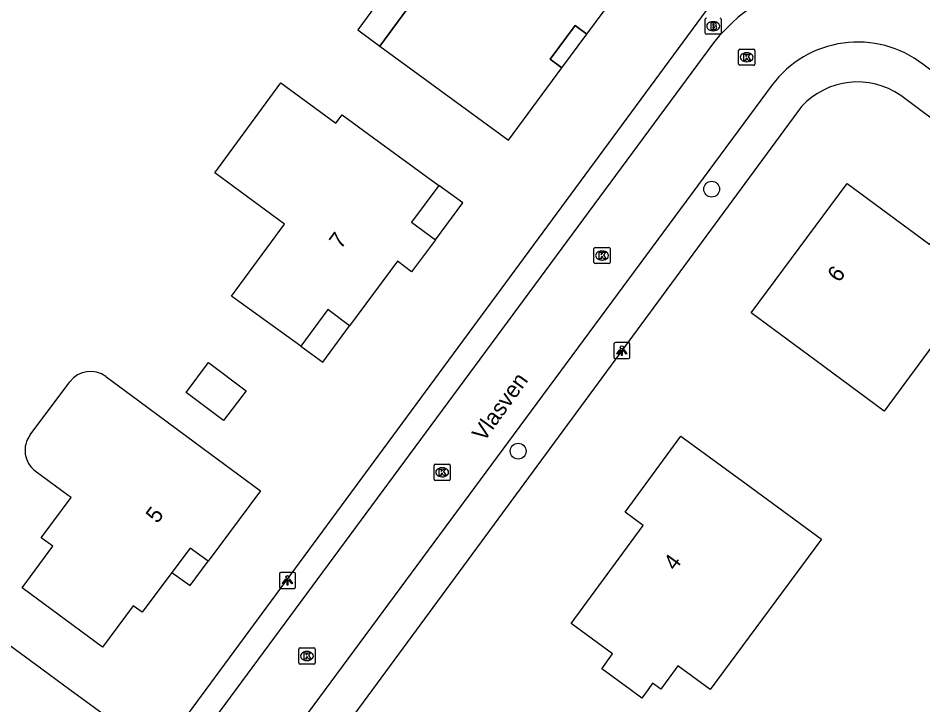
# Model space of a CAD drawing. Extents: x 163427 to 164190, y 380331 to 381641.
# Drawn here: x 163847.7 to 163903.8, y 381499 to 381541.6 of the extents above; entities that cross this region are included whole.
import ezdxf

# ---------------------------------------------------------------- set-up
doc = ezdxf.new("R2010")
doc.units = 0
for name, color, linetype in [('IMGEO_Boom', 7, 'Continuous'), ('IMGEO_Brandkraan', 7, 'Continuous'), ('IMGEO_Kolk', 7, 'Continuous'), ('IMGEO_Lichtpunt', 7, 'Continuous'), ('IMGEO_Openbare_ruimte_label', 7, 'Continuous'), ('IMGEO_Pand', 7, 'Continuous'), ('IMGEO_Pand_nummerreeks', 7, 'Continuous'), ('IMGEO_Pand_overbouw', 7, 'Continuous'), ('IMGEO_Rijbaan_lokaal_open', 7, 'Continuous'), ('IMGEO_Voetpad_open', 7, 'Continuous')]:
    doc.layers.add(name, color=color, linetype=linetype)

msp = doc.modelspace()

# ---------------------------------------------------------------- linework, layer by layer
at = {"layer": 'IMGEO_Boom'}
for centre in [(163890.661, 381530.995), (163878.665, 381514.767)]:
    msp.add_circle(centre, 0.489, dxfattribs=at)
at = {"layer": 'IMGEO_Brandkraan'}
for p, q in [((163890.257, 381540.666), (163890.257, 381541.518)), ((163890.745, 381541.372), (163890.77, 381541.372)), ((163891.258, 381541.518), (163891.258, 381540.666)), ((163891.184, 381540.592), (163890.332, 381540.592)), ((163890.768, 381540.812), (163890.743, 381540.812))]:
    msp.add_line(p, q, dxfattribs=at)
for points in [[(163890.257, 381540.666), (163890.257, 381541.518)], [(163890.605, 381541.292), (163890.605, 381540.892), (163890.818, 381540.892)], [(163890.836, 381541.292), (163890.605, 381541.292)], [(163890.784, 381541.211), (163890.73, 381541.211), (163890.73, 381541.135)], [(163890.73, 381541.135), (163890.783, 381541.135)], [(163891.258, 381541.518), (163891.258, 381540.666)], [(163891.184, 381540.592), (163890.332, 381540.592)], [(163890.792, 381541.059), (163890.73, 381541.059), (163890.73, 381540.978)], [(163890.73, 381540.978), (163890.792, 381540.978)]]:
    msp.add_lwpolyline(points, dxfattribs=at)
for centre, radius, start, end in [((163890.334, 381541.516), 0.0765, 91.552, 178.448), ((163890.334, 381541.516), 0.0765, 91.552, 178.448), ((163890.785, 381541.173), 0.0379, 267.8285, 90.9355), ((163890.84, 381541.147), 0.145, 59.4692, 91.5367), ((163890.865, 381541.194), 0.0922, 285.5137, 58.1501), ((163890.87, 381541.002), 0.105, 301.3115, 78.989), ((163891.182, 381541.516), 0.0765, 1.552, 88.448), ((163891.182, 381541.516), 0.0765, 1.552, 88.448), ((163890.334, 381540.668), 0.0765, 181.552, 268.448), ((163890.334, 381540.668), 0.0765, 181.552, 268.448), ((163890.793, 381541.018), 0.0404, 269.8759, 90.5077), ((163890.824, 381541.143), 0.251, 268.6676, 293.5347), ((163891.182, 381540.668), 0.0765, 271.552, 358.448), ((163891.182, 381540.668), 0.0765, 271.552, 358.448)]:
    msp.add_arc(centre, radius, start, end, dxfattribs=at)
for centre, major_axis, ratio, start_param, end_param in [((163890.744, 381541.092), (-0.387, 0.002), 0.722429, 4.712389, 7.853982), ((163890.769, 381541.092), (-0.39, 0.002), 0.717154, 1.570796, 4.712389)]:
    msp.add_ellipse(centre, major_axis=major_axis, ratio=ratio, start_param=start_param, end_param=end_param, dxfattribs=at)
at = {"layer": 'IMGEO_Kolk'}
for p, q in [((163892.333, 381538.741), (163892.333, 381539.593)), ((163892.408, 381539.667), (163893.26, 381539.667)), ((163892.821, 381539.447), (163892.846, 381539.447)), ((163893.334, 381539.593), (163893.334, 381538.741)), ((163892.844, 381538.887), (163892.819, 381538.887)), ((163893.26, 381538.667), (163892.408, 381538.667)), ((163883.366, 381526.458), (163883.366, 381527.31)), ((163883.441, 381527.384), (163884.293, 381527.384)), ((163883.854, 381527.164), (163883.879, 381527.164)), ((163884.367, 381527.31), (163884.367, 381526.458)), ((163883.877, 381526.604), (163883.852, 381526.604)), ((163884.293, 381526.384), (163883.441, 381526.384)), ((163873.455, 381513.029), (163873.455, 381513.881)), ((163873.53, 381513.955), (163874.382, 381513.955)), ((163873.943, 381513.735), (163873.968, 381513.735)), ((163874.456, 381513.881), (163874.456, 381513.029)), ((163873.966, 381513.175), (163873.941, 381513.175)), ((163874.382, 381512.955), (163873.53, 381512.955)), ((163865.075, 381501.65), (163865.075, 381502.502)), ((163865.15, 381502.576), (163866.002, 381502.576)), ((163866.076, 381502.502), (163866.076, 381501.65)), ((163865.563, 381502.356), (163865.588, 381502.356)), ((163866.002, 381501.576), (163865.15, 381501.576)), ((163865.586, 381501.796), (163865.561, 381501.796))]:
    msp.add_line(p, q, dxfattribs=at)
for points in [[(163892.333, 381538.741), (163892.333, 381539.593)], [(163892.408, 381539.667), (163893.26, 381539.667)], [(163893.334, 381539.593), (163893.334, 381538.741)], [(163892.654, 381539.367), (163892.777, 381539.367), (163892.777, 381539.216), (163892.907, 381539.367), (163893.071, 381539.367), (163892.925, 381539.216), (163893.078, 381538.967), (163892.926, 381538.967), (163892.841, 381539.131), (163892.777, 381539.064), (163892.777, 381538.967), (163892.654, 381538.967), (163892.654, 381539.367)], [(163893.26, 381538.667), (163892.408, 381538.667)], [(163883.366, 381526.458), (163883.366, 381527.31)], [(163883.441, 381527.384), (163884.293, 381527.384)], [(163883.687, 381527.084), (163883.81, 381527.084), (163883.81, 381526.933), (163883.94, 381527.084), (163884.104, 381527.084), (163883.958, 381526.933), (163884.111, 381526.684), (163883.959, 381526.684), (163883.874, 381526.848), (163883.81, 381526.781), (163883.81, 381526.684), (163883.687, 381526.684), (163883.687, 381527.084)], [(163884.367, 381527.31), (163884.367, 381526.458)], [(163884.293, 381526.384), (163883.441, 381526.384)], [(163873.455, 381513.029), (163873.455, 381513.881)], [(163873.53, 381513.955), (163874.382, 381513.955)], [(163873.776, 381513.655), (163873.899, 381513.655), (163873.899, 381513.504), (163874.029, 381513.655), (163874.193, 381513.655), (163874.047, 381513.504), (163874.2, 381513.255), (163874.048, 381513.255), (163873.963, 381513.419), (163873.899, 381513.352), (163873.899, 381513.255), (163873.776, 381513.255), (163873.776, 381513.655)], [(163874.456, 381513.881), (163874.456, 381513.029)], [(163874.382, 381512.955), (163873.53, 381512.955)], [(163865.075, 381501.65), (163865.075, 381502.502)], [(163865.15, 381502.576), (163866.002, 381502.576)], [(163866.076, 381502.502), (163866.076, 381501.65)], [(163865.396, 381502.276), (163865.519, 381502.276), (163865.519, 381502.125), (163865.649, 381502.276), (163865.813, 381502.276), (163865.667, 381502.125), (163865.82, 381501.876), (163865.668, 381501.876), (163865.583, 381502.04), (163865.519, 381501.973), (163865.519, 381501.876), (163865.396, 381501.876), (163865.396, 381502.276)], [(163866.002, 381501.576), (163865.15, 381501.576)]]:
    msp.add_lwpolyline(points, dxfattribs=at)
for centre, start, end in [((163892.41, 381539.591), 91.552, 178.448), ((163892.41, 381539.591), 91.552, 178.448), ((163893.258, 381539.591), 1.552, 88.448), ((163893.258, 381539.591), 1.552, 88.448), ((163892.41, 381538.743), 181.552, 268.448), ((163892.41, 381538.743), 181.552, 268.448), ((163893.258, 381538.743), 271.552, 358.448), ((163893.258, 381538.743), 271.552, 358.448), ((163883.443, 381527.308), 91.552, 178.448), ((163883.443, 381527.308), 91.552, 178.448), ((163884.291, 381527.308), 1.552, 88.448), ((163884.291, 381527.308), 1.552, 88.448), ((163883.443, 381526.46), 181.552, 268.448), ((163883.443, 381526.46), 181.552, 268.448), ((163884.291, 381526.46), 271.552, 358.448), ((163884.291, 381526.46), 271.552, 358.448), ((163873.532, 381513.879), 91.552, 178.448), ((163873.532, 381513.879), 91.552, 178.448), ((163874.38, 381513.879), 1.552, 88.448), ((163874.38, 381513.879), 1.552, 88.448), ((163873.532, 381513.031), 181.552, 268.448), ((163873.532, 381513.031), 181.552, 268.448), ((163874.38, 381513.031), 271.552, 358.448), ((163874.38, 381513.031), 271.552, 358.448), ((163865.152, 381502.5), 91.552, 178.448), ((163865.152, 381502.5), 91.552, 178.448), ((163866, 381502.5), 1.552, 88.448), ((163866, 381502.5), 1.552, 88.448), ((163865.152, 381501.652), 181.552, 268.448), ((163865.152, 381501.652), 181.552, 268.448), ((163866, 381501.652), 271.552, 358.448), ((163866, 381501.652), 271.552, 358.448)]:
    msp.add_arc(centre, 0.0765, start, end, dxfattribs=at)
for centre, major_axis, ratio, start_param, end_param in [((163892.82, 381539.167), (-0.387, 0.002), 0.722429, 4.712389, 7.853982), ((163892.845, 381539.167), (-0.39, 0.002), 0.717154, 1.570796, 4.712389), ((163883.853, 381526.884), (-0.387, 0.002), 0.722429, 4.712389, 7.853982), ((163883.878, 381526.884), (-0.39, 0.002), 0.717154, 1.570796, 4.712389), ((163873.942, 381513.455), (-0.387, 0.002), 0.722429, 4.712389, 7.853982), ((163873.967, 381513.455), (-0.39, 0.002), 0.717154, 1.570796, 4.712389), ((163865.562, 381502.076), (-0.387, 0.002), 0.722429, 4.712389, 7.853982), ((163865.587, 381502.076), (-0.39, 0.002), 0.717154, 1.570796, 4.712389)]:
    msp.add_ellipse(centre, major_axis=major_axis, ratio=ratio, start_param=start_param, end_param=end_param, dxfattribs=at)
at = {"layer": 'IMGEO_Lichtpunt'}
for p, q in [((163885.5, 381521.493), (163884.692, 381521.493)), ((163885.5, 381521.493), (163884.692, 381521.493)), ((163884.598, 381521.398), (163884.598, 381520.591)), ((163884.598, 381521.398), (163884.598, 381520.591)), ((163885.594, 381520.591), (163885.594, 381521.398)), ((163885.594, 381520.591), (163885.594, 381521.398)), ((163884.692, 381520.497), (163885.5, 381520.497)), ((163884.692, 381520.497), (163885.5, 381520.497)), ((163863.872, 381507.163), (163863.872, 381506.356)), ((163863.872, 381507.163), (163863.872, 381506.356)), ((163864.774, 381507.258), (163863.966, 381507.258)), ((163864.774, 381507.258), (163863.966, 381507.258)), ((163864.868, 381506.356), (163864.868, 381507.163)), ((163864.868, 381506.356), (163864.868, 381507.163)), ((163863.966, 381506.262), (163864.774, 381506.262)), ((163863.966, 381506.262), (163864.774, 381506.262))]:
    msp.add_line(p, q, dxfattribs=at)
for points in [[(163884.972, 381521.062), (163885.011, 381521.034), (163884.823, 381520.772), (163884.785, 381520.799), (163884.972, 381521.062)], [(163885.074, 381521.014), (163885.121, 381521.014), (163885.121, 381520.692), (163885.074, 381520.692), (163885.074, 381521.014)], [(163885.184, 381521.034), (163885.222, 381521.061), (163885.409, 381520.799), (163885.37, 381520.771), (163885.184, 381521.034)], [(163864.246, 381506.827), (163864.285, 381506.799), (163864.097, 381506.537), (163864.059, 381506.564), (163864.246, 381506.827)], [(163864.348, 381506.779), (163864.395, 381506.779), (163864.395, 381506.457), (163864.348, 381506.457), (163864.348, 381506.779)], [(163864.458, 381506.799), (163864.496, 381506.826), (163864.683, 381506.564), (163864.644, 381506.536), (163864.458, 381506.799)]]:
    msp.add_lwpolyline(points, dxfattribs=at)
for centre in [(163885.097, 381521.196), (163864.371, 381506.961)]:
    msp.add_circle(centre, 0.0994, dxfattribs=at)
for centre, start, end in [((163884.692, 381521.398), 90, 180), ((163884.692, 381521.398), 90, 180), ((163885.5, 381521.398), 0, 90), ((163885.5, 381521.398), 0, 90), ((163884.692, 381520.591), 180, 270), ((163884.692, 381520.591), 180, 270), ((163885.5, 381520.591), 270, 0), ((163885.5, 381520.591), 270, 360), ((163863.966, 381507.163), 90, 180), ((163863.966, 381507.163), 90, 180), ((163864.774, 381507.163), 0, 90), ((163864.774, 381507.163), 0, 90), ((163863.966, 381506.356), 180, 270), ((163863.966, 381506.356), 180, 270), ((163864.774, 381506.356), 270, 0), ((163864.774, 381506.356), 270, 360)]:
    msp.add_arc(centre, 0.0946, start, end, dxfattribs=at)
at = {"layer": 'IMGEO_Pand'}
for points in [[(163885.134, 381543.598), (163884.411, 381544.139), (163886.651, 381547.183), (163878.013, 381553.503), (163873.967, 381548.003), (163875.336, 381546.996), (163870.088, 381539.863), (163878.075, 381534.033), (163881.383, 381538.512), (163880.659, 381539.043), (163882.193, 381541.135), (163882.917, 381540.604), (163885.134, 381543.598)], [(163863.955, 381537.584), (163867.372, 381535.079), (163867.756, 381535.603), (163869.706, 381534.179), (163873.745, 381531.231), (163872.061, 381528.943), (163873.543, 381527.854), (163872.059, 381525.879), (163871.179, 381526.544), (163868.22, 381522.526), (163866.871, 381523.534), (163865.194, 381521.278), (163861.133, 381524.195), (163860.901, 381524.362), (163864.18, 381528.834), (163859.861, 381532), (163863.955, 381537.584)], [(163893.11, 381523.329), (163899.061, 381531.355), (163904.178, 381527.56), (163906.144, 381530.211), (163911.608, 381526.146), (163908.633, 381522.128), (163907.092, 381520.047), (163904.725, 381521.799), (163901.344, 381517.233), (163897.129, 381520.354), (163893.11, 381523.329)], [(163858.092, 381518.409), (163859.482, 381520.251), (163861.803, 381518.498), (163860.412, 381516.657), (163858.092, 381518.409)], [(163853.106, 381519.385), (163855.151, 381517.873), (163858.667, 381515.274), (163862.687, 381512.301), (163859.454, 381507.944), (163858.345, 381508.762), (163857.206, 381507.247), (163855.358, 381504.789), (163854.811, 381505.192), (163852.913, 381502.617), (163847.922, 381506.296), (163849.819, 381508.871), (163849.1, 381509.401), (163850.96, 381511.893), (163850.784, 381512.024), (163848.739, 381513.536)], [(163848.42, 381515.768), (163850.885, 381519.068)], [(163886.329, 381499.47), (163885.605, 381500), (163883.847, 381501.287), (163884.519, 381502.205), (163881.957, 381504.081), (163886.423, 381510.156), (163885.294, 381510.986), (163888.76, 381515.686), (163892.793, 381512.731), (163897.466, 381509.306), (163890.56, 381500), (163888.557, 381501.465), (163887.501, 381500.022), (163887.001, 381500.388), (163886.717, 381500), (163886.329, 381499.47)], [(163840.559, 381501.215), (163838.613, 381502.64), (163838.821, 381502.925), (163841.407, 381506.456), (163844.537, 381504.165), (163844.768, 381504.479), (163849.138, 381501.28), (163850.887, 381500), (163853.173, 381498.327), (163849.649, 381493.564), (163848.827, 381494.174), (163843.461, 381486.835), (163839.432, 381489.796), (163835.871, 381492.414), (163832.768, 381494.662), (163835.495, 381498.386), (163837.444, 381496.96), (163840.559, 381501.215)]]:
    msp.add_lwpolyline(points, dxfattribs=at)
for centre, radius, start, end in [((163852.155, 381518.111), 1.59, 53.2529, 142.9928), ((163849.691, 381514.811), 1.591, 143.0283, 233.2391)]:
    msp.add_arc(centre, radius, start, end, dxfattribs=at)
at = {"layer": 'IMGEO_Pand_overbouw'}
for points in [[(163873.967, 381548.003), (163868.719, 381540.87), (163870.088, 381539.863), (163875.336, 381546.996)], [(163882.917, 381540.604), (163882.193, 381541.135), (163880.659, 381539.043), (163881.383, 381538.512)], [(163873.543, 381527.854), (163875.237, 381530.141), (163873.745, 381531.231), (163872.061, 381528.943)], [(163868.22, 381522.526), (163866.871, 381523.534), (163865.194, 381521.278), (163866.562, 381520.271)], [(163857.206, 381507.247), (163858.332, 381506.451), (163859.454, 381507.944), (163858.345, 381508.762)]]:
    msp.add_lwpolyline(points, close=True, dxfattribs=at)
at = {"layer": 'IMGEO_Rijbaan_lokaal_open'}
for points in [[(163890.772, 381540.06), (163861.162, 381500), (163854.341, 381490.772)], [(163947.52, 381492.105), (163941.609, 381500), (163923.926, 381523.619), (163903.754, 381538.74)], [(163894.412, 381537.451), (163866.707, 381500), (163857.987, 381488.213)]]:
    msp.add_lwpolyline(points, dxfattribs=at)
for centre, radius, start, end in [((163899.786, 381532.832), 11.554, 56.0565, 141.2748), ((163899.719, 381533.488), 6.623, 52.4635, 143.2485)]:
    msp.add_arc(centre, radius, start, end, dxfattribs=at)
at = {"layer": 'IMGEO_Voetpad_open'}
for points in [[(163853.125, 381491.594), (163859.32, 381500), (163894.099, 381547.191)], [(163938.652, 381500), (163922.256, 381521.933), (163902.379, 381536.794)], [(163896.233, 381536.108), (163869.633, 381500), (163859.926, 381486.823)]]:
    msp.add_lwpolyline(points, dxfattribs=at)
msp.add_arc((163899.696, 381532.952), 4.685, 55.0739, 137.6638, dxfattribs=at)

# ---------------------------------------------------------------- texts
at = {"layer": 'IMGEO_Openbare_ruimte_label'}
msp.add_text('Vlasven', height=1, rotation=54.1959, dxfattribs=at).set_placement((163876.547, 381515.299))
at = {"layer": 'IMGEO_Pand_nummerreeks'}
for s, rotation, p in [('7', 53.6464, (163867.677, 381527.239)), ('6', 53.4444, (163898.556, 381525.167)), ('5', 53.0632, (163856.302, 381510.238)), ('4', 53.6788, (163888.4, 381507.307))]:
    msp.add_text(s, height=1, rotation=rotation, dxfattribs=at).set_placement(p)

doc.saveas('drawing.dxf')
